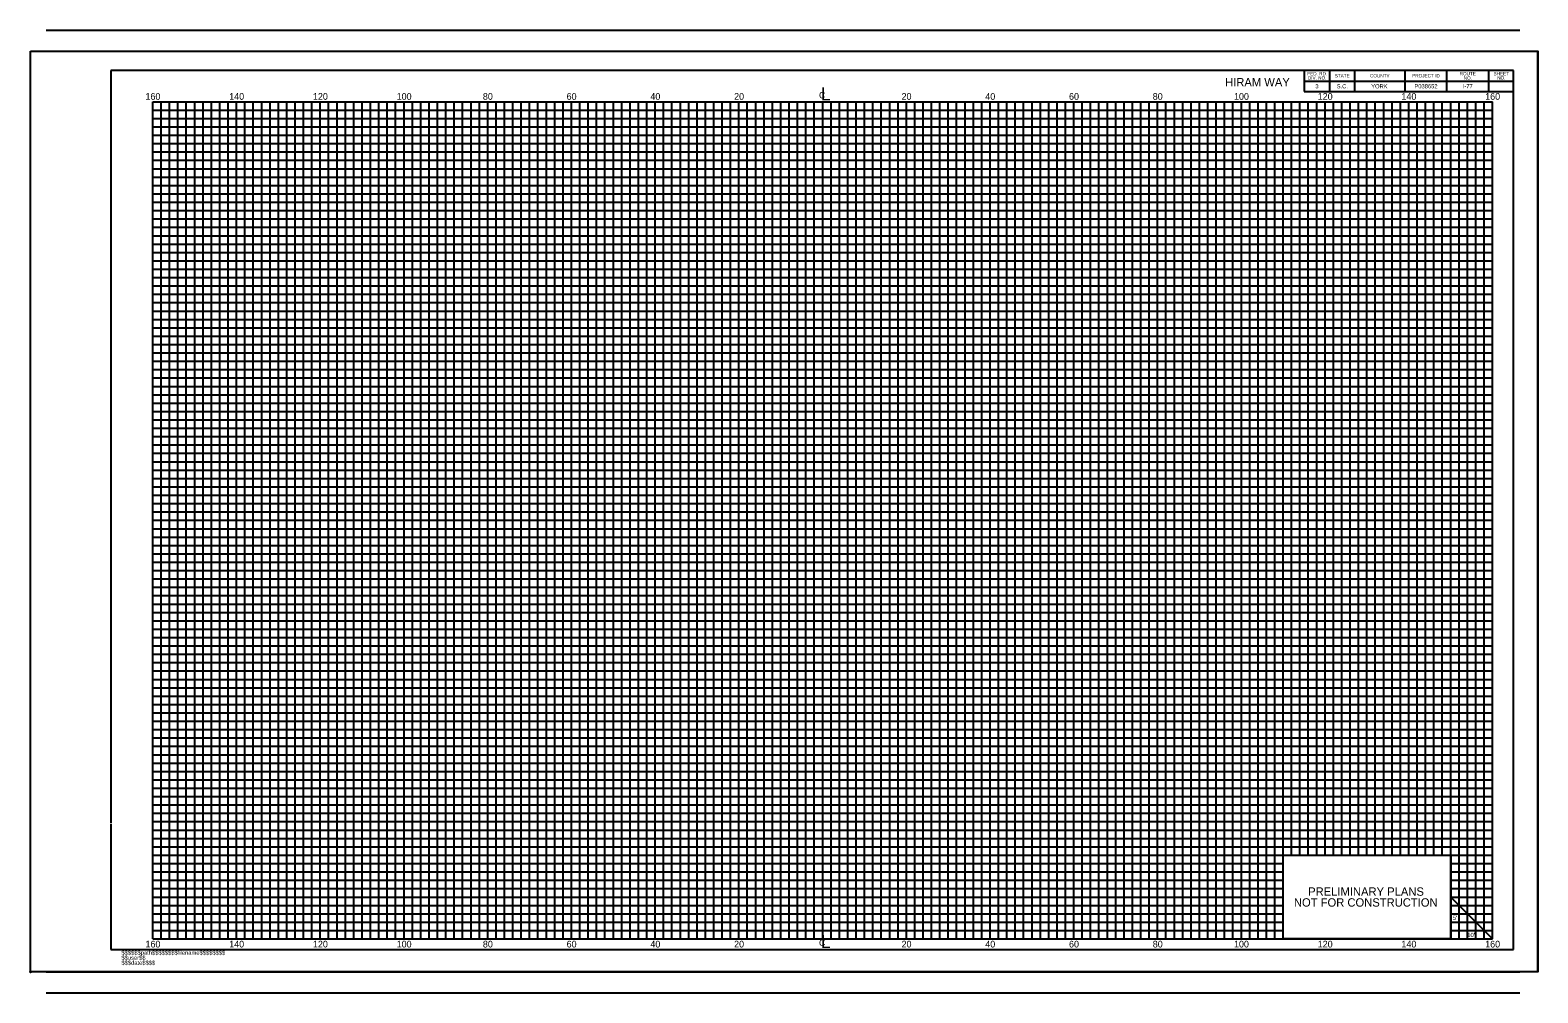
# Model space of a CAD drawing. Extents: x -15 to 165, y -6 to 109.
import ezdxf

# ---------------------------------------------------------------- set-up
doc = ezdxf.new("R2010")
doc.units = 0
for name, color, linetype in [('RD_DDB_StaTX', 7, 'Continuous'), ('RD_SHT_Bndy', 7, 'Continuous'), ('RD_SHT_ID', 7, 'Continuous'), ('RD_SHT_IplotShp', 7, 'Continuous'), ('RD_SHT_MjGrid_XS', 7, 'Continuous'), ('RD_SHT_MnGrid_XS', 7, 'Continuous'), ('RD_SHT_Snap', 7, 'Continuous'), ('RD_SHT_TX', 7, 'Continuous')]:
    doc.layers.add(name, color=color, linetype=linetype)

msp = doc.modelspace()

# ---------------------------------------------------------------- linework, layer by layer
at = {"layer": 'RD_SHT_Bndy'}
for p, q in [((-12.73, 108.55), (163.27, 108.55)), ((-12.73, 106.05), (163.27, 106.05)), ((-5, 103.72), (-5, 13.81)), ((162.51, 103.72), (-5, 103.72)), ((137.51, 103.72), (137.51, 101.22)), ((140.51, 103.72), (140.51, 101.22)), ((143.51, 103.72), (143.51, 101.22)), ((149.51, 103.72), (149.51, 101.22)), ((154.51, 103.72), (154.51, 101.22)), ((159.51, 103.72), (159.51, 101.22)), ((162.51, -1.28), (162.51, 103.72)), ((137.51, 102.47), (162.51, 102.47)), ((137.51, 101.22), (162.51, 101.22)), ((-5, 13.72), (-5, -1.28)), ((139.95, 5), (139.95, 5)), ((145, 5), (145, 5)), ((-5, -1.28), (162.51, -1.28)), ((-12.73, -3.95), (163.27, -3.95)), ((-12.73, -6.45), (163.27, -6.45))]:
    msp.add_line(p, q, dxfattribs=at)
msp.add_lwpolyline([(135, 10), (155, 10), (155, 0), (135, 0)], close=True, dxfattribs=at)
at = {"layer": 'RD_SHT_IplotShp'}
msp.add_lwpolyline([(-14.59, 106.05), (165.41, 106.05), (165.41, -3.95), (-14.59, -3.95)], close=True, dxfattribs=at)
at = {"layer": 'RD_SHT_MjGrid_XS'}
for p, q in [((0, 100), (160, 100)), ((0, 0), (0, 100)), ((5, 0), (5, 100)), ((10, 0), (10, 100)), ((15, 0), (15, 100)), ((20, 0), (20, 100)), ((25, 0), (25, 100)), ((30, 0), (30, 100)), ((35, 0), (35, 100)), ((40, 0), (40, 100)), ((45, 0), (45, 100)), ((50, 0), (50, 100)), ((55, 0), (55, 100)), ((60, 0), (60, 100)), ((65, 0), (65, 100)), ((70, 0), (70, 100)), ((75, 0), (75, 100)), ((80, 0), (80, 100)), ((85, 0), (85, 100)), ((90, 0), (90, 100)), ((95, 0), (95, 100)), ((100, 0), (100, 100)), ((105, 0), (105, 100)), ((110, 0), (110, 100)), ((115, 0), (115, 100)), ((120, 0), (120, 100)), ((125, 0), (125, 100)), ((130, 0), (130, 100)), ((135, 0), (135, 100)), ((140, 10), (140, 100)), ((145, 10), (145, 100)), ((150, 10), (150, 100)), ((155, 0), (155, 100)), ((160, 0), (160, 100)), ((0, 95), (160, 95)), ((0, 90), (160, 90)), ((0, 85), (160, 85)), ((0, 80), (160, 80)), ((0, 75), (160, 75)), ((0, 70), (160, 70)), ((0, 65), (160, 65)), ((0, 60), (160, 60)), ((0, 55), (160, 55)), ((0, 50), (160, 50)), ((0, 45), (160, 45)), ((0, 40), (160, 40)), ((0, 35), (160, 35)), ((0, 30), (160, 30)), ((0, 25), (160, 25)), ((0, 20), (160, 20)), ((0, 15), (160, 15)), ((0, 10), (160, 10)), ((0, 5), (135, 5)), ((155, 5), (160, 0)), ((155, 5), (160, 5)), ((0, 0), (160, 0))]:
    msp.add_line(p, q, dxfattribs=at)
at = {"layer": 'RD_SHT_MnGrid_XS'}
for p, q in [((1, 0), (1, 100)), ((2, 0), (2, 100)), ((3, 0), (3, 100)), ((4, 0), (4, 100)), ((6, 0), (6, 100)), ((7, 0), (7, 100)), ((8, 0), (8, 100)), ((9, 0), (9, 100)), ((11, 0), (11, 100)), ((12, 0), (12, 100)), ((13, 0), (13, 100)), ((14, 0), (14, 100)), ((16, 0), (16, 100)), ((17, 0), (17, 100)), ((18, 0), (18, 100)), ((19, 0), (19, 100)), ((21, 0), (21, 100)), ((22, 0), (22, 100)), ((23, 0), (23, 100)), ((24, 0), (24, 100)), ((26, 0), (26, 100)), ((27, 0), (27, 100)), ((28, 0), (28, 100)), ((29, 0), (29, 100)), ((31, 0), (31, 100)), ((32, 0), (32, 100)), ((33, 0), (33, 100)), ((34, 0), (34, 100)), ((36, 0), (36, 100)), ((37, 0), (37, 100)), ((38, 0), (38, 100)), ((39, 0), (39, 100)), ((41, 0), (41, 100)), ((42, 0), (42, 100)), ((43, 0), (43, 100)), ((44, 0), (44, 100)), ((46, 0), (46, 100)), ((47, 0), (47, 100)), ((48, 0), (48, 100)), ((49, 0), (49, 100)), ((51, 0), (51, 100)), ((52, 0), (52, 100)), ((53, 0), (53, 100)), ((54, 0), (54, 100)), ((56, 0), (56, 100)), ((57, 0), (57, 100)), ((58, 0), (58, 100)), ((59, 0), (59, 100)), ((61, 0), (61, 100)), ((62, 0), (62, 100)), ((63, 0), (63, 100)), ((64, 0), (64, 100)), ((66, 0), (66, 100)), ((67, 0), (67, 100)), ((68, 0), (68, 100)), ((69, 0), (69, 100)), ((71, 0), (71, 100)), ((72, 0), (72, 100)), ((73, 0), (73, 100)), ((74, 0), (74, 100)), ((76, 0), (76, 100)), ((77, 0), (77, 100)), ((78, 0), (78, 100)), ((79, 0), (79, 100)), ((81, 0), (81, 100)), ((82, 0), (82, 100)), ((83, 0), (83, 100)), ((84, 0), (84, 100)), ((86, 0), (86, 100)), ((87, 0), (87, 100)), ((88, 0), (88, 100)), ((89, 0), (89, 100)), ((91, 0), (91, 100)), ((92, 0), (92, 100)), ((93, 0), (93, 100)), ((94, 0), (94, 100)), ((96, 0), (96, 100)), ((97, 0), (97, 100)), ((98, 0), (98, 100)), ((99, 0), (99, 100)), ((101, 0), (101, 100)), ((102, 0), (102, 100)), ((103, 0), (103, 100)), ((104, 0), (104, 100)), ((106, 0), (106, 100)), ((107, 0), (107, 100)), ((108, 0), (108, 100)), ((109, 0), (109, 100)), ((111, 0), (111, 100)), ((112, 0), (112, 100)), ((113, 0), (113, 100)), ((114, 0), (114, 100)), ((116, 0), (116, 100)), ((117, 0), (117, 100)), ((118, 0), (118, 100)), ((119, 0), (119, 100)), ((121, 0), (121, 100)), ((122, 0), (122, 100)), ((123, 0), (123, 100)), ((124, 0), (124, 100)), ((126, 0), (126, 100)), ((127, 0), (127, 100)), ((128, 0), (128, 100)), ((129, 0), (129, 100)), ((131, 0), (131, 100)), ((132, 0), (132, 100)), ((133, 0), (133, 100)), ((134, 0), (134, 100)), ((136, 10), (136, 100)), ((137, 10), (137, 100)), ((138, 10), (138, 100)), ((139, 10), (139, 100)), ((141, 10), (141, 100)), ((142, 10), (142, 100)), ((143, 10), (143, 100)), ((144, 10), (144, 100)), ((146, 10), (146, 100)), ((147, 10), (147, 100)), ((148, 10), (148, 100)), ((149, 10), (149, 100)), ((151, 10), (151, 100)), ((152, 10), (152, 100)), ((153, 10), (153, 100)), ((154, 10), (154, 100)), ((156, 0), (156, 100)), ((157, 0), (157, 100)), ((158, 0), (158, 100)), ((159, 0), (159, 100)), ((0, 99), (160, 99)), ((0, 98), (160, 98)), ((0, 97), (160, 97)), ((0, 96), (160, 96)), ((0, 94), (160, 94)), ((0, 93), (160, 93)), ((0, 92), (160, 92)), ((0, 91), (160, 91)), ((0, 89), (160, 89)), ((0, 88), (160, 88)), ((0, 87), (160, 87)), ((0, 86), (160, 86)), ((0, 84), (160, 84)), ((0, 83), (160, 83)), ((0, 82), (160, 82)), ((0, 81), (160, 81)), ((0, 79), (160, 79)), ((0, 78), (160, 78)), ((0, 77), (160, 77)), ((0, 76), (160, 76)), ((0, 74), (160, 74)), ((0, 73), (160, 73)), ((0, 72), (160, 72)), ((0, 71), (160, 71)), ((0, 69), (160, 69)), ((0, 68), (160, 68)), ((0, 67), (160, 67)), ((0, 66), (160, 66)), ((0, 64), (160, 64)), ((0, 63), (160, 63)), ((0, 62), (160, 62)), ((0, 61), (160, 61)), ((0, 59), (160, 59)), ((0, 58), (160, 58)), ((0, 57), (160, 57)), ((0, 56), (160, 56)), ((0, 54), (160, 54)), ((0, 53), (160, 53)), ((0, 52), (160, 52)), ((0, 51), (160, 51)), ((0, 49), (160, 49)), ((0, 48), (160, 48)), ((0, 47), (160, 47)), ((0, 46), (160, 46)), ((0, 44), (160, 44)), ((0, 43), (160, 43)), ((0, 42), (160, 42)), ((0, 41), (160, 41)), ((0, 39), (160, 39)), ((0, 38), (160, 38)), ((0, 37), (160, 37)), ((0, 36), (160, 36)), ((0, 34), (160, 34)), ((0, 33), (160, 33)), ((0, 32), (160, 32)), ((0, 31), (160, 31)), ((0, 29), (160, 29)), ((0, 28), (160, 28)), ((0, 27), (160, 27)), ((0, 26), (160, 26)), ((0, 24), (160, 24)), ((0, 23), (160, 23)), ((0, 22), (160, 22)), ((0, 21), (160, 21)), ((0, 21), (160, 21)), ((0, 19), (160, 19)), ((0, 18), (160, 18)), ((0, 17), (160, 17)), ((0, 16), (160, 16)), ((0, 14), (160, 14)), ((0, 13), (160, 13)), ((0, 12), (160, 12)), ((0, 11), (160, 11)), ((0, 9), (135, 9)), ((0, 8), (135, 8)), ((155, 9), (160, 9)), ((155, 8), (160, 8)), ((0, 7), (135, 7)), ((0, 6), (135, 6)), ((155, 7), (160, 7)), ((155, 6), (160, 6)), ((0, 4), (135, 4)), ((155, 4), (160, 4)), ((0, 3), (135, 3)), ((0, 2), (135, 2)), ((155, 3), (160, 3)), ((155, 2), (160, 2)), ((0, 1), (135, 1)), ((155, 1), (160, 1))]:
    msp.add_line(p, q, dxfattribs=at)
at = {"layer": 'RD_SHT_Snap'}
for p, q in [((-14.59, -3.95), (-14.59, 106.05)), ((165.41, -3.95), (165.41, 106.05))]:
    msp.add_line(p, q, dxfattribs=at)
msp.add_circle((-14.59, -3.95), 0.0607, dxfattribs=at)

# ---------------------------------------------------------------- texts
at = {"layer": 'RD_DDB_StaTX'}
for s, height, p in [('160', 0.8, (-0.88, 100.23)), ('140', 0.8, (9.12, 100.23)), ('120', 0.8, (19.12, 100.23)), ('100', 0.8, (29.12, 100.23)), ('80', 0.8, (39.42, 100.23)), ('60', 0.8, (49.42, 100.23)), ('40', 0.8, (59.42, 100.23)), ('20', 0.8, (69.42, 100.23)), ('C', 0.773, (79.56, 100.4)), ('L', 1.55, (79.79, 100.16)), ('20', 0.8, (89.42, 100.23)), ('40', 0.8, (99.42, 100.23)), ('60', 0.8, (109.42, 100.23)), ('80', 0.8, (119.42, 100.23)), ('100', 0.8, (129.12, 100.23)), ('120', 0.8, (139.12, 100.23)), ('140', 0.8, (149.12, 100.23)), ('160', 0.8, (159.12, 100.23)), ('L', 1.55, (79.79, -1.09)), ('160', 0.8, (-0.88, -1.03)), ('140', 0.8, (9.12, -1.03)), ('120', 0.8, (19.12, -1.03)), ('100', 0.8, (29.12, -1.03)), ('80', 0.8, (39.42, -1.03)), ('60', 0.8, (49.42, -1.03)), ('40', 0.8, (59.42, -1.03)), ('20', 0.8, (69.42, -1.03)), ('C', 0.773, (79.56, -0.85)), ('20', 0.8, (89.42, -1.03)), ('40', 0.8, (99.42, -1.03)), ('60', 0.8, (109.42, -1.03)), ('80', 0.8, (119.42, -1.03)), ('100', 0.8, (129.12, -1.03)), ('120', 0.8, (139.12, -1.03)), ('140', 0.8, (149.12, -1.03)), ('160', 0.8, (159.12, -1.03))]:
    msp.add_text(s, height=height, dxfattribs=at).set_placement(p)
at = {"layer": 'RD_SHT_ID'}
for s, p in [('$$$$$$path$$$$$$$$filename$$$$$$$$', (-3.75, -1.9)), ('$$user$$', (-3.75, -2.5)), ('$$$date$$$$', (-3.75, -3.1))]:
    msp.add_text(s, height=0.5, rotation=360, dxfattribs=at).set_placement(p)
at = {"layer": 'RD_SHT_TX'}
for s, height, p in [('HIRAM WAY', 1, (128.06, 101.83)), ('FED. RD.', 0.4, (137.88, 103.15)), ('DIV. NO.', 0.4, (137.95, 102.65)), ('STATE', 0.4, (141.15, 102.9)), ('COUNTY', 0.4, (145.37, 102.9)), ('PROJECT ID', 0.4, (150.41, 102.9)), ('ROUTE', 0.4, (156.07, 103.15)), ('NO.', 0.4, (156.56, 102.63)), ('SHEET', 0.4, (160.12, 103.15)), ('NO.', 0.4, (160.56, 102.65)), ('3', 0.5, (138.84, 101.6)), ('S.C.', 0.5, (141.39, 101.6)), ('YORK', 0.5, (145.51, 101.6)), ('P038652', 0.5, (150.67, 101.6)), ('I-77', 0.5, (156.44, 101.6)), ('PRELIMINARY PLANS', 1, (137.98, 5.15)), ('NOT FOR CONSTRUCTION', 1, (136.28, 3.85)), ("5'", 0.512, (155.26, 2.26)), ("10'", 0.512, (156.97, 0.21))]:
    msp.add_text(s, height=height, dxfattribs=at).set_placement(p)

doc.saveas('drawing.dxf')
